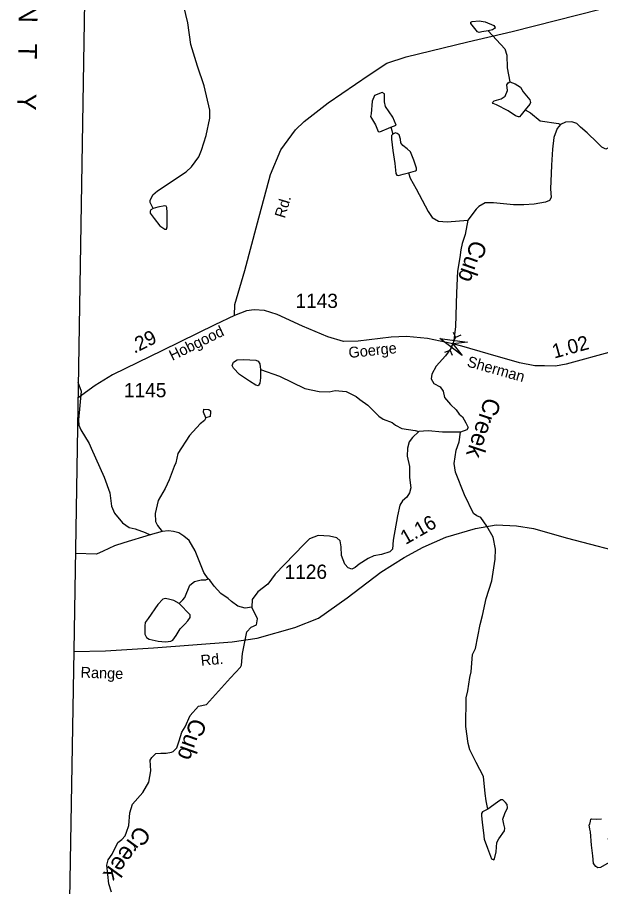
# Model space of a CAD drawing. Extents: x 2056842 to 2160602, y 826753 to 1016856.
# Drawn here: x 2058229 to 2063341, y 926037 to 933655 of the extents above; entities that cross this region are included whole.
import ezdxf

# ---------------------------------------------------------------- set-up
doc = ezdxf.new("R2010")
doc.units = 0
for name, color, linetype in [('Exist Boundary Political CountyLine', 7, 'Continuous'), ('Exist Boundary Political CountyLine Label', 7, 'Continuous'), ('Exist Hydrographic Creek Single Shore', 7, 'Continuous'), ('Exist Hydrographic Creek Single Shore Label', 7, 'Continuous'), ('Exist Hydrographic Misc Water Feature', 7, 'Continuous'), ('Exist Road Secondary Mileage Hundredths English Label', 7, 'Continuous'), ('Exist Road Secondary Structure Pipe Attributed CELL', 7, 'Continuous'), ('Exist Road Secondary Structure Pipe CELL', 7, 'Continuous'), ('Exist Road Secondary Type 51 Attributed', 7, 'Continuous'), ('Exist Road Secondary Type 51 Label', 7, 'Continuous'), ('Exist Road Secondary Type 51 Number Label', 7, 'Continuous')]:
    doc.layers.add(name, color=color, linetype=linetype)

msp = doc.modelspace()

# ---------------------------------------------------------------- linework, layer by layer
at = {"layer": 'Exist Boundary Political CountyLine'}
msp.add_lwpolyline([(2059856.6, 1016190.3), (2059992.1, 1014583.5), (2060287.9, 1010619.4), (2060242.2, 1008370.9), (2060207.5, 1006770.5), (2060178.3, 1005306.3), (2060151, 1003993.9), (2060126.7, 1003051.7), (2060085.9, 1001469.5), (2060082.6, 1001042.9), (2059970.1, 996247.2), (2059900.3, 992964.9), (2059780.5, 986400.7), (2059706.7, 983126.5), (2059583, 976558.1), (2059387.4, 966719.6), (2059309.7, 963431.4), (2059197.6, 956451.1), (2059161.2, 955539), (2058926.7, 940379.5), (2058724.8, 928102.2), (2058408.1, 910016.3), (2058297.2, 904795.7)], dxfattribs=at)
at = {"layer": 'Exist Hydrographic Creek Single Shore'}
for points in [[(2059419.2, 931980.9), (2059392.6, 932030.9), (2059392.6, 932050.9), (2059416.4, 932098.9), (2059456.4, 932135.1), (2059708, 932299.5), (2059756, 932345.6), (2059819.7, 932433.6), (2059843.7, 932489.7), (2059883.5, 932619.8), (2059915.1, 932769.9), (2059915.1, 932841.9), (2059866.7, 933053.7), (2059806.4, 933225.7), (2059750, 933415.5), (2059721.7, 933607.6), (2059689.3, 933751.4)], [(2063595.8, 933280.5), (2063561.9, 933272.6), (2063524.5, 933197.4), (2063496.9, 933132.1), (2063469.4, 933052.4), (2063486.7, 932924.4), (2063488.8, 932832.5), (2063498.9, 932800.4), (2063511.7, 932713), (2063491.2, 932656.7), (2063447.7, 932567.1), (2063423.4, 932519.7), (2063386.3, 932500.5), (2063353.1, 932518.5), (2063309.6, 932556.9), (2063222.6, 932641.4), (2063163.7, 932693.8), (2063131.7, 932723.3), (2063089.5, 932738.6), (2063033.2, 932734.8), (2062989.7, 932716.9)], [(2062989.7, 932716.9), (2062959, 932681), (2062929.6, 932601.7), (2062918.1, 932500.5), (2062910.6, 932360.4), (2062908, 932284.9), (2062902.9, 932153), (2062908, 932076.2), (2062893.9, 932049.3), (2062856.8, 932035.2), (2062759.6, 932018.6), (2062668.8, 932012.2), (2062577.9, 932010.9), (2062401.1, 932030.1), (2062329.5, 932030.1), (2062274.5, 931996.8), (2062248.9, 931972.5), (2062177.4, 931876.5)], [(2062177.4, 931876.5), (2062153.1, 931752.4), (2062128.8, 931673), (2062114.7, 931618), (2062107, 931548.8), (2062087.5, 931431.8), (2062078.9, 931239.7), (2062069.9, 930944.6), (2062053.3, 930821.8), (2062045.7, 930793.8), (2062029, 930753.9), (2061980.4, 930687.4), (2061901.1, 930597.8), (2061861.4, 930528.6), (2061855, 930487.7), (2061879.3, 930446.7), (2061934.3, 930416.6), (2061961.2, 930379.5), (2061974, 930323.2), (2062023.9, 930262.4), (2062076.3, 930215), (2062100.6, 930176.6), (2062131.4, 930153.6), (2062159.5, 930099.8), (2062180, 930058.9), (2062169.7, 930039.7), (2062113.4, 930019.2)], [(2061746.9, 930023.9), (2061692.3, 929972.5), (2061662.9, 929934.1), (2061648.2, 929879.7), (2061646.9, 929810.5), (2061666.1, 929717.1), (2061666.1, 929621.1), (2061677.6, 929531.5), (2061667.4, 929489.2), (2061643.1, 929450.8), (2061603.4, 929418.8), (2061581.6, 929380.4), (2061561.2, 929285.7), (2061522.5, 929073.9), (2061516.2, 928994.5), (2061493.1, 928971.5), (2061421.5, 928947.1), (2061352.4, 928935.6), (2061302.5, 928912.6), (2061224.5, 928861.4), (2061189.9, 928833.2), (2061161.8, 928819.1), (2061128.5, 928829.4), (2061100.4, 928861.4), (2061069.7, 928939.5), (2061068.4, 929015), (2061059.6, 929066.2), (2061028.9, 929094.3), (2060966.2, 929107.1), (2060865.1, 929113.5), (2060789.7, 929085.4), (2060738.6, 929034.2), (2060489.2, 928774.3), (2060425.2, 928686), (2060336.9, 928620.7), (2060288.1, 928554.2), (2060285, 928486.6)], [(2062113.4, 930019.2), (2062062.3, 930018.5), (2061954.6, 930018.5), (2061829.2, 930030.1), (2061746.9, 930023.9)], [(2059496.7, 929149.4), (2059394.4, 929119.9), (2059162.8, 929050.8), (2059080.9, 929022.7), (2058982.4, 928976.6), (2058923.6, 928951), (2058738.8, 928954.7)], [(2059900.6, 928733.8), (2059864.4, 928789.7), (2059846.2, 928833.7), (2059787.1, 928980.4), (2059734.6, 929071.3), (2059688.6, 929108.4), (2059645.1, 929136.6), (2059596.5, 929149.4), (2059554.3, 929154.5), (2059496.7, 929149.4)], [(2060285, 928486.6), (2060225.1, 928478.3), (2060161.1, 928494.1), (2060104.8, 928534.3), (2060076.9, 928562.1), (2060012.8, 928606.1), (2059952.8, 928669.7), (2059916.4, 928721.7), (2059900.6, 928733.8)]]:
    msp.add_lwpolyline(points, dxfattribs=at)
at = {"layer": 'Exist Hydrographic Misc Water Feature'}
msp.add_line((2059880, 930145.9), (2059859.9, 930195.8), dxfattribs=at)
for points in [[(2062355.2, 933537.3), (2062298.7, 933527.2), (2062275.5, 933522.8), (2062261, 933528.6), (2062203.1, 933599.7), (2062204.5, 933611.3), (2062214.7, 933617.1), (2062275.5, 933624.3), (2062330.6, 933615.6), (2062405.9, 933582.3), (2062416.1, 933564.9), (2062411.7, 933556.2), (2062394.3, 933546), (2062355.2, 933537.3)], [(2062355.2, 933537.3), (2062501.8, 933378.7), (2062518, 933322.6), (2062521.8, 933213.3), (2062546.5, 933090.1)], [(2062679.8, 932843.6), (2062645, 932800.1), (2062629.1, 932782.7), (2062621.8, 932782.7), (2062595.7, 932792.9), (2062532, 932834.9), (2062429.1, 932887.1), (2062398.7, 932898.7), (2062394.3, 932907.4), (2062407.4, 932921.9), (2062468.2, 932940.8), (2062503, 932964), (2062526.2, 933013.3), (2062520.4, 933064), (2062532, 933079.9), (2062546.5, 933090.1)], [(2062546.5, 933090.1), (2062592.8, 933071.2), (2062637.8, 933043.7), (2062662.4, 933003.1), (2062721.8, 932930.6), (2062727.6, 932907.4), (2062721.8, 932894.4), (2062679.8, 932843.6)], [(2061446.8, 932914.7), (2061446.8, 932984.7), (2061426.7, 932996.6), (2061358.9, 932968.5), (2061339, 932920.5), (2061329.1, 932808.6)], [(2061501.4, 932692.8), (2061549.4, 932710.9), (2061521.3, 932778.9), (2061454.8, 932872.8), (2061446.8, 932914.7)], [(2061329.1, 932808.6), (2061325.2, 932784.5), (2061367.6, 932713.7), (2061391.9, 932653.5), (2061404.7, 932651), (2061501.4, 932692.8)], [(2062679.8, 932843.6), (2062727, 932817.1), (2062811.2, 932747.3), (2062971.2, 932723.6), (2062989.7, 932716.9)], [(2061501.4, 932692.8), (2061505.3, 932684.8), (2061519.8, 932631.4)], [(2061519.8, 932631.4), (2061508.3, 932619), (2061508.3, 932586.9), (2061521.1, 932488.4), (2061537.8, 932373.2), (2061545.4, 932286.1), (2061554.4, 932270.8), (2061569.8, 932269.5), (2061610.7, 932281), (2061656, 932293.2)], [(2061656, 932293.2), (2061719.4, 932310.5), (2061728.4, 932316.9), (2061728.4, 932332.2), (2061702.8, 932403.9), (2061675.9, 932476.9), (2061646.5, 932502.5), (2061606.8, 932530.6), (2061590.2, 932554.9), (2061586.4, 932586.9), (2061576.1, 932624.1), (2061558.2, 932638.2), (2061542.9, 932642), (2061519.8, 932631.4)], [(2061656, 932293.2), (2061672.2, 932245.2), (2061724.3, 932153.2), (2061828.6, 931953.5), (2061864.7, 931901.5), (2061920.7, 931869.7), (2061996.8, 931861.8), (2062177.4, 931876.5)], [(2059419.2, 931980.9), (2059398.7, 931969.3), (2059392.3, 931955.3), (2059392.3, 931939.9), (2059428.1, 931891.3), (2059476.7, 931827.3), (2059521.5, 931797.8), (2059535.6, 931799.1), (2059543.3, 931818.3), (2059543.3, 931943.7), (2059539.4, 931989.8), (2059534.3, 932000.1), (2059520.2, 932002.6), (2059460.1, 931992.4), (2059419.2, 931980.9)], [(2060360.1, 930569), (2060360.1, 930494.7), (2060353.7, 930449.9), (2060340.9, 930426.9), (2060320.4, 930430.7), (2060262.8, 930465.3), (2060175.9, 930525.4), (2060124.7, 930579.2), (2060111.9, 930604.8), (2060124.7, 930631.7), (2060156.7, 930652.2), (2060214.2, 930656), (2060317.9, 930650.9), (2060338.3, 930640.6), (2060353.7, 930617.6), (2060360.1, 930569)], [(2060360.1, 930569), (2060525.5, 930511.1), (2060749.7, 930401.5), (2060873.5, 930375.7), (2060961.7, 930371.8), (2061013.6, 930386), (2061109.5, 930376.2), (2061197.7, 930332.3), (2061229.7, 930304.4), (2061301.9, 930256.5), (2061398, 930160.6), (2061434.1, 930134.7), (2061514.1, 930102.9), (2061542.2, 930081), (2061598.2, 930051), (2061714.2, 930035.4), (2061746.9, 930023.9)], [(2058759.1, 930458.8), (2058787.7, 930379.8), (2058766.2, 930127.7), (2058768.2, 930079.8), (2058786.3, 930039.9), (2058858.7, 929919.9), (2058874.7, 929880), (2058991.1, 929624.2), (2059039.3, 929488.3), (2059055.5, 929370.3), (2059079.7, 929308.3), (2059151.9, 929224.5), (2059209.9, 929184.6), (2059262, 929172.8), (2059348.3, 929139.1), (2059394.4, 929119.9)], [(2059859.9, 930195.8), (2059864, 930219.8), (2059907.9, 930218), (2059921.9, 930206), (2059921.9, 930194)], [(2059880, 930145.9), (2059868.1, 930121.9), (2059832.2, 930093.8), (2059736.5, 929989.6), (2059634.8, 929833.4), (2059618.8, 929749.4), (2059603, 929717.3), (2059559.1, 929601.3), (2059523.2, 929525.2), (2059463.4, 929421.1), (2059435.7, 929307.1), (2059439.8, 929237.1), (2059455.8, 929201.1), (2059496.7, 929149.4)], [(2059921.9, 930194), (2059920, 930158), (2059880, 930145.9)], [(2062351.4, 926715.4), (2062337.3, 926787.1), (2062328.1, 926852.5), (2062315.8, 927000.5), (2062249.6, 927124.4), (2062193.4, 927236.3), (2062181.3, 927292.3), (2062159, 927440.2), (2062162.7, 927690.2), (2062178.5, 927752.2), (2062194.2, 927868.3), (2062206.1, 927920.2), (2062217.8, 928072.3), (2062245.7, 928124.4), (2062285.3, 928332.4), (2062307.2, 928412.5), (2062337, 928560.5), (2062388.6, 928716.6), (2062416.3, 928906.6), (2062420, 928992.7), (2062399.9, 929100.6), (2062343.7, 929196.5), (2062291.6, 929270.4), (2062255.6, 929286.3), (2062227.5, 929306.3), (2062147.1, 929470.1), (2062069, 929670), (2062056.7, 929745.9), (2062076.3, 929861.7), (2062101.9, 929936), (2062113.4, 930019.2)], [(2059647.7, 928519), (2059678.4, 928551), (2059697.1, 928569.5), (2059740.8, 928677.6), (2059780.8, 928709.7), (2059840.7, 928725.8), (2059880.6, 928725.9), (2059900.7, 928734)], [(2059647.7, 928519), (2059600.3, 928543.3), (2059554.3, 928556.1), (2059523.6, 928562.5), (2059503.1, 928554.8), (2059459.6, 928508.7), (2059375.2, 928385.8), (2059357.3, 928364.1), (2059349.6, 928351.3), (2059347, 928323.1), (2059347, 928248.9), (2059361.1, 928219.4), (2059384.1, 928205.3), (2059463.4, 928188.7), (2059526.1, 928182.3), (2059574.7, 928188.7), (2059592.6, 928196.4), (2059620.8, 928238.6), (2059655.3, 928296.2), (2059696.3, 928337.2), (2059723.1, 928366.6), (2059742.3, 928394.8), (2059743.6, 928419.1), (2059647.7, 928519)], [(2059053.9, 925988.3), (2059029.7, 926060.4), (2059013.5, 926224.4), (2059025.4, 926272.3), (2059061.3, 926320.4), (2059109, 926424.5), (2059144.9, 926448.6), (2059173, 926480.7), (2059184.9, 926512.7), (2059204.8, 926572.7), (2059214.6, 926684.7), (2059238.4, 926758.7), (2059328.2, 926862.9), (2059380.1, 926951.1), (2059399.8, 927051), (2059391.8, 927145), (2059407.8, 927167.1), (2059443.7, 927203.1), (2059487.6, 927207.3), (2059534.3, 927205.6), (2059579.1, 927214.6), (2059595.6, 927219.4), (2059627.4, 927253.5), (2059647.3, 927313.5), (2059671.3, 927389.6), (2059699.3, 927436), (2059743.1, 927537.7), (2059817.3, 927617.8), (2059887.6, 927631.9), (2060097.4, 927867.4), (2060185.7, 927960.9), (2060193.4, 927976.2), (2060201.1, 928080.5), (2060240.7, 928270), (2060277.8, 928309.7), (2060323.9, 928330.2), (2060332.8, 928382.6), (2060285.2, 928486.6)], [(2062351.4, 926715.4), (2062306.6, 926691), (2062297.7, 926677), (2062296.4, 926660.3), (2062302.8, 926598.9), (2062315.6, 926509.3), (2062319.4, 926453), (2062348.8, 926374.9), (2062385.9, 926278.9), (2062403.8, 926272.5), (2062410.2, 926281.4), (2062424.3, 926341.6), (2062432, 926422.2), (2062448.6, 926455.5), (2062498.5, 926525.9), (2062502.3, 926550.2), (2062492.1, 926583.5), (2062484.4, 926627), (2062502.3, 926677), (2062525.4, 926728.2), (2062522.8, 926755.1), (2062508.7, 926774.3), (2062483.2, 926796), (2062466.5, 926796), (2062437.1, 926778.1), (2062351.4, 926715.4)], [(2063407.5, 926462.6), (2063416.5, 926384.5), (2063431.9, 926298.7), (2063426.7, 926270.6), (2063415.2, 926248.8), (2063339.7, 926204), (2063315.4, 926201.4), (2063298.8, 926213), (2063279.6, 926239.8), (2063271.9, 926307.7), (2063260.4, 926401.1), (2063252.8, 926517.6), (2063245.1, 926539.4), (2063240, 926579), (2063246.4, 926585.4), (2063252.8, 926611.1), (2063254, 926627.7), (2063260.4, 926630.3), (2063302.6, 926627.7), (2063348.7, 926631.5)]]:
    msp.add_lwpolyline(points, dxfattribs=at)
at = {"layer": 'Exist Road Secondary Structure Pipe Attributed CELL'}
msp.add_lwpolyline([(2062127.4, 930692.6), (2061932.7, 930839.6), (2062174.7, 930809.6), (2062045.7, 930793.8)], close=True, dxfattribs=at)
at = {"layer": 'Exist Road Secondary Structure Pipe CELL'}
for p, q in [((2062023.1, 930737.7), (2062068.4, 930849.9)), ((2062047.3, 930896), (2062068.4, 930849.9)), ((2062115.6, 930868.4), (2062068.4, 930849.9)), ((2061975.9, 930719.2), (2062023.1, 930737.7)), ((2062044.2, 930691.5), (2062023.1, 930737.7))]:
    msp.add_line(p, q, dxfattribs=at)
at = {"layer": 'Exist Road Secondary Type 51 Attributed'}
for points in [[(2060130.8, 931043), (2060135.3, 931139.5), (2060221.9, 931435.6), (2060334.1, 931855.4), (2060446.3, 932278.1), (2060538.2, 932493.6), (2060666.2, 932670), (2060741.9, 932743.3), (2060953, 932904.9), (2061312, 933150.5), (2061467.1, 933254.6), (2061636.6, 933309), (2062176.3, 933441), (2062566.5, 933532.2), (2063338.1, 933726.6)], [(2063444.9, 930727.1), (2063038.2, 930614.8), (2062944.9, 930598.7), (2062847.9, 930600.5), (2062765.3, 930600.5), (2062630.6, 930627.4), (2062354.1, 930704.7), (2062124.3, 930773), (2062045.7, 930793.8), (2061823.5, 930840.3), (2061640.4, 930856.5), (2061503.9, 930851.1), (2061216.6, 930817), (2061087.3, 930815.2), (2060949.9, 930855.6), (2060729.1, 930949), (2060506.4, 931049.7), (2060395.1, 931085.6), (2060303.5, 931092.8), (2060237.1, 931082), (2060130.8, 931043)], [(2060130.8, 931043), (2059959.7, 930960.7), (2059500, 930734.3), (2059061.8, 930521.8), (2058911, 930428.9), (2058761.3, 930320.4)], [(2058724.7, 928096.3), (2059000.5, 928102.9), (2059422.4, 928129.9), (2060111.1, 928182.9), (2060331.9, 928215.2), (2060660.5, 928308.7), (2060867, 928389.5), (2061119.3, 928568.3), (2061413.8, 928792.9), (2061618.5, 928922.3), (2061784.6, 929013), (2061985.7, 929099.3), (2062244.3, 929176.5), (2062426.5, 929206.2), (2062604.3, 929199), (2062751.6, 929175.6), (2063051.4, 929089.4), (2063631.4, 928938.5), (2063797.5, 928887.2), (2064057.9, 928836.9), (2064294.9, 928810), (2064536.7, 928802.7)]]:
    msp.add_lwpolyline(points, dxfattribs=at)

# ---------------------------------------------------------------- texts
at = {"layer": 'Exist Boundary Political CountyLine Label'}
msp.add_text('C   O   U   N   T     Y', height=164.042, rotation=269.03226, dxfattribs=at).set_placement((2058261.2, 934802.6))
at = {"layer": 'Exist Hydrographic Creek Single Shore Label'}
for s, rotation, p in [('Cub', 250.55002, (2062209.4, 931712.2)), ('Creek', 251.55825, (2062329.8, 930332.6)), ('Cub', 250.5206, (2059751.1, 927522.6)), ('Creek', 233.86218, (2059289.5, 926582.3))]:
    msp.add_text(s, height=150, rotation=rotation, dxfattribs=at).set_placement(p)
at = {"layer": 'Exist Road Secondary Mileage Hundredths English Label'}
for s, rotation, p in [('.29', 26.29963, (2059253.6, 930706.1)), ('1.02', 15.38921, (2062935.1, 930663.7)), ('1.16', 29.76733, (2061631.4, 929030.1))]:
    msp.add_text(s, height=125, rotation=rotation, dxfattribs=at).set_placement(p)
at = {"layer": 'Exist Road Secondary Type 51 Label'}
for s, rotation, p in [('Rd.', 73.39872, (2060572.8, 931889.1)), ('Hobgood', 26.29971, (2059587.7, 930642.9)), ('Goerge', 5.83964, (2061136.2, 930669.1)), ('Sherman', 344.31821, (2062163.9, 930596.6)), ('Rd.', 5.62088, (2059840.5, 927970.7)), ('Range', 358.09793, (2058781.5, 927868.4))]:
    msp.add_text(s, height=95, rotation=rotation, dxfattribs=at).set_placement(p)
at = {"layer": 'Exist Road Secondary Type 51 Number Label'}
for s, p in [('1143', (2060666.5, 931107.9)), ('1145', (2059163.2, 930325.6)), ('1126', (2060571.4, 928733.7))]:
    msp.add_text(s, height=125, dxfattribs=at).set_placement(p)

doc.saveas('drawing.dxf')
